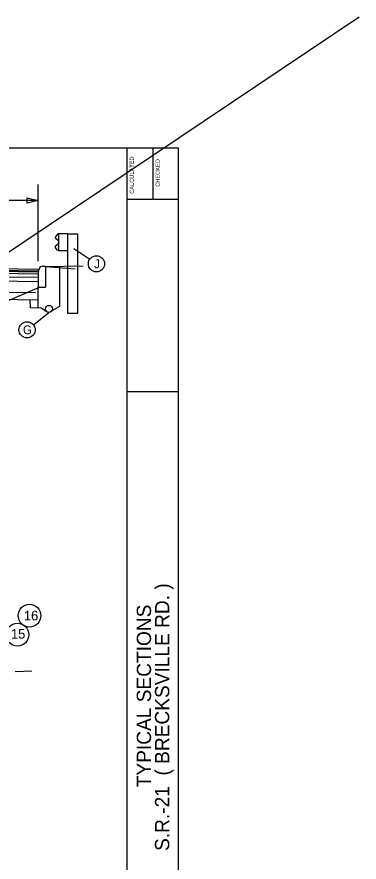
# Model space of a CAD drawing. Extents: x 227 to 993, y -530 to -180.
# Drawn here: x 430.2 to 457, y -485.8 to -419.6 of the extents above; entities that cross this region are included whole.
import ezdxf

# ---------------------------------------------------------------- set-up
doc = ezdxf.new("R2010")
doc.units = 0
for name, color, linetype in [('Default', 7, 'Continuous'), ('Level 1', 7, 'Continuous'), ('Level 11', 7, 'Continuous'), ('Level 59', 7, 'Continuous')]:
    doc.layers.add(name, color=color, linetype=linetype)

msp = doc.modelspace()

# ---------------------------------------------------------------- linework, layer by layer
at = {"layer": 'Default'}
for centre in [(431.17, -466.501), (430.22, -467.992)]:
    msp.add_circle(centre, 0.892, dxfattribs=at)
at = {"layer": 'Level 1'}
for p, q in [((316.833, -429.85), (442.833, -429.85)), ((438.833, -446.85), (438.833, -429.85)), ((440.833, -429.85), (440.833, -433.85)), ((442.833, -429.85), (442.833, -513.85)), ((438.833, -433.85), (442.833, -433.85)), ((438.833, -491.85), (438.833, -446.85)), ((438.833, -448.938), (442.833, -448.938)), ((431.349, -470.839), (430.043, -470.901))]:
    msp.add_line(p, q, dxfattribs=at)
at = {"layer": 'Level 11'}
for p, q in [((292.845, -529.603), (457.012, -419.578)), ((433.357, -436.608), (433.194, -436.833)), ((433.42, -437.113), (433.211, -436.951)), ((433.453, -436.591), (433.357, -436.608)), ((434.186, -436.591), (433.453, -436.591)), ((433.453, -436.591), (433.453, -437.875)), ((434.186, -439.066), (434.186, -436.591)), ((434.186, -436.591), (434.92, -436.591)), ((434.92, -436.591), (434.92, -439.066)), ((433.357, -437.858), (433.194, -437.633)), ((433.211, -437.515), (433.42, -437.352)), ((433.453, -437.875), (433.357, -437.858)), ((433.453, -437.875), (434.186, -437.875)), ((418.552, -439.136), (431.855, -439.335)), ((418.555, -439.136), (431.915, -439.336)), ((432.186, -439.11), (432.388, -439.11)), ((432.411, -439.133), (435.384, -439.086)), ((432.411, -439.133), (432.411, -440.761)), ((432.437, -439.132), (434.753, -439.327)), ((433.518, -439.115), (433.518, -442.269)), ((434.186, -442.825), (434.186, -439.066)), ((434.92, -439.066), (434.92, -442.825)), ((418.552, -439.343), (431.881, -439.542)), ((418.552, -439.352), (431.879, -439.551)), ((418.552, -439.506), (431.855, -439.704)), ((418.552, -439.785), (431.855, -439.984)), ((418.553, -439.274), (431.892, -439.473)), ((431.848, -439.737), (431.915, -439.34)), ((431.848, -439.737), (431.848, -440.761)), ((418.552, -440.11), (431.855, -440.309)), ((418.552, -440.99), (431.645, -441.186)), ((431.848, -440.761), (432.411, -440.761)), ((431.86, -442.401), (431.848, -440.761)), ((418.552, -441.546), (431.855, -441.745)), ((431.237, -442.374), (431.232, -441.735)), ((432.085, -442.408), (431.237, -442.374)), ((432.537, -442.68), (432.085, -442.408)), ((433.518, -442.269), (432.731, -442.729)), ((434.92, -442.825), (434.186, -442.825))]:
    msp.add_line(p, q, dxfattribs=at)
for centre, radius in [((436.419, -438.928), 0.636), ((432.696, -442.457), 0.275), ((430.979, -444.102), 0.636)]:
    msp.add_circle(centre, radius, dxfattribs=at)
for centre, radius, start, end in [((433.264, -436.883), 0.0859, 144.08393, 232.1285), ((433.367, -437.181), 0.0859, 360, 52.13216), ((433.264, -437.582), 0.0859, 127.8715, 215.91607), ((433.367, -437.284), 0.0859, 307.8715, 0), ((432.186, -439.385), 0.275, 90, 170.53768), ((432.388, -439.133), 0.0229, 0, 90)]:
    msp.add_arc(centre, radius, start, end, dxfattribs=at)
at = {"layer": 'Level 59'}
for p, q in [((431.848, -438.732), (431.848, -432.711)), ((431.848, -433.959), (418.552, -433.959)), ((431.848, -433.959), (418.552, -433.959)), ((435.887, -438.579), (434.64, -437.761)), ((428.14, -442.384), (431.943, -440.761)), ((431.474, -443.701), (432.673, -442.731))]:
    msp.add_line(p, q, dxfattribs=at)
msp.add_lwpolyline([(430.992, -433.745), (431.848, -433.959), (430.992, -434.173)], close=True, dxfattribs=at)

# ---------------------------------------------------------------- texts
at = {"layer": 'Default'}
for s, p in [('16', (430.731, -466.872)), ('15', (429.717, -468.305))]:
    msp.add_text(s, height=0.755, dxfattribs=at).set_placement(p)
at = {"layer": 'Level 1'}
for s, height, p in [('CALCULATED', 0.32, (439.35, -433.436)), ('CHECKED', 0.32, (441.372, -432.887)), ('S.R.-21  ( BRECKSVILLE RD. )', 1.12, (442.128, -484.94)), ('TYPICAL SECTIONS', 1.12, (440.699, -479.949))]:
    msp.add_text(s, height=height, rotation=90, dxfattribs=at).set_placement(p)
at = {"layer": 'Level 59'}
for s, p in [('J', (436.235, -439.271)), ('G', (430.652, -444.445))]:
    msp.add_text(s, height=0.686, dxfattribs=at).set_placement(p)

doc.saveas('drawing.dxf')
